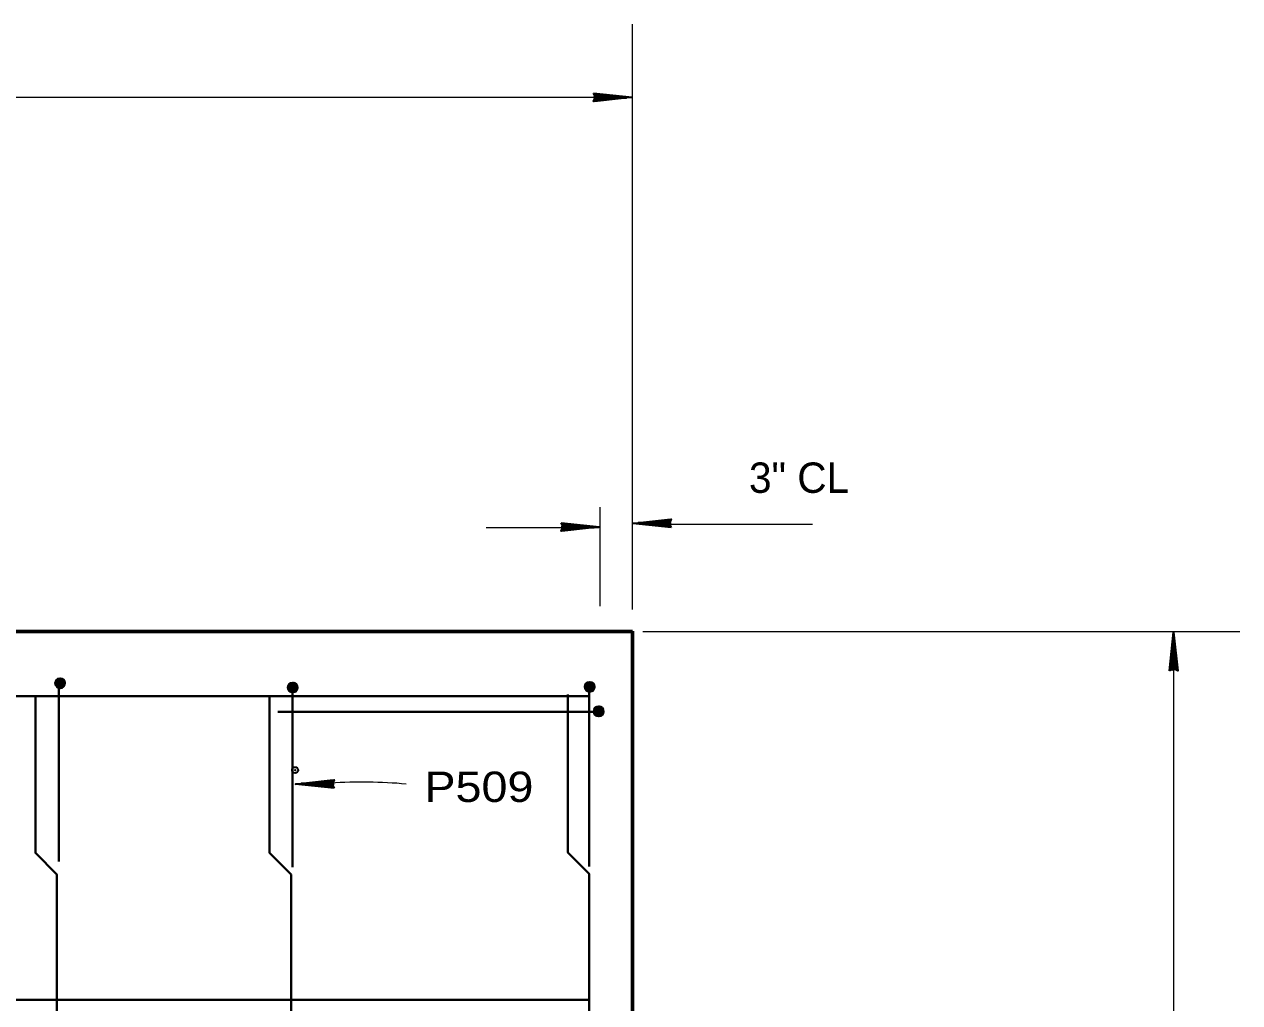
# Model space of a CAD drawing. Extents: x 4.49 to 7.69, y 0.28 to 2.27.
# Drawn here: x 5.2955 to 5.6291, y 0.9139 to 1.1824 of the extents above; entities that cross this region are included whole.
import ezdxf

# ---------------------------------------------------------------- set-up
doc = ezdxf.new("R2010")
doc.units = 0
doc.header["$LTSCALE"] = 0.0033
doc.header["$PDMODE"] = 32
doc.header["$PDSIZE"] = 0.00165
doc.layers.add('1', color=7, linetype='Continuous', lineweight=35)

msp = doc.modelspace()

# ---------------------------------------------------------------- linework, layer by layer
at = {"layer": '1', "lineweight": 13}
for p, q in [((5.462417, 1.021833), (5.462417, 1.182417)), ((5.453583, 1.02275), (5.453583, 1.049917)), ((5.462417, 1.049083), (5.462417, 1.049417)), ((5.462417, 1.049083), (5.4625, 1.049083)), ((5.42225, 1.044333), (5.453167, 1.044333)), ((5.473083, 1.04525), (5.511833, 1.04525)), ((5.46525, 1.01575), (5.629083, 1.01575)), ((5.610917, 1.013917), (5.610917, 0.599083))]:
    msp.add_line(p, q, dxfattribs=at)
at = {"layer": '1'}
for p, q in [((5.45175, 1.162417), (5.462333, 1.162417)), ((5.451917, 1.16175), (5.45925, 1.1625)), ((5.452, 1.163417), (5.459833, 1.1625)), ((5.452, 1.163417), (5.459833, 1.1625)), ((5.452, 1.163333), (5.459833, 1.1625)), ((5.452, 1.16325), (5.459833, 1.162417)), ((5.452, 1.16325), (5.459833, 1.16225)), ((5.452, 1.161583), (5.459333, 1.162417)), ((5.452, 1.1615), (5.459333, 1.16225)), ((5.452, 1.161333), (5.459333, 1.162167)), ((5.442833, 1.0445), (5.453417, 1.0445)), ((5.443, 1.043833), (5.450333, 1.044583)), ((5.443083, 1.0455), (5.450917, 1.044583)), ((5.443083, 1.0455), (5.450917, 1.044583)), ((5.443083, 1.045417), (5.450917, 1.044583)), ((5.443083, 1.045333), (5.450917, 1.0445)), ((5.443083, 1.045333), (5.450917, 1.044333)), ((5.443083, 1.043667), (5.450417, 1.0445)), ((5.443083, 1.043583), (5.450417, 1.044333)), ((5.443083, 1.043417), (5.450417, 1.04425)), ((5.473083, 1.045417), (5.4625, 1.045417)), ((5.472833, 1.044583), (5.465, 1.045583)), ((5.472833, 1.044583), (5.465, 1.045417)), ((5.472833, 1.044417), (5.465, 1.045333)), ((5.472833, 1.044417), (5.465, 1.045333)), ((5.472833, 1.0445), (5.465, 1.045333)), ((5.472833, 1.0465), (5.4655, 1.045667)), ((5.472833, 1.046333), (5.4655, 1.045583)), ((5.472833, 1.04625), (5.4655, 1.045417)), ((5.472917, 1.046083), (5.465583, 1.045333)), ((5.610917, 1.005), (5.610917, 1.015583)), ((5.609917, 1.00525), (5.610833, 1.013083)), ((5.609917, 1.00525), (5.610833, 1.013083)), ((5.61, 1.00525), (5.610833, 1.013083)), ((5.610083, 1.00525), (5.610917, 1.013083)), ((5.610083, 1.00525), (5.611083, 1.013083)), ((5.611583, 1.005167), (5.610833, 1.0125)), ((5.61175, 1.00525), (5.610917, 1.012583)), ((5.611833, 1.00525), (5.611083, 1.012583)), ((5.612, 1.00525), (5.611167, 1.012583)), ((5.380333, 0.973083), (5.3725, 0.974083)), ((5.380333, 0.975), (5.373, 0.974167)), ((5.380333, 0.974833), (5.373, 0.974083)), ((5.380333, 0.97475), (5.373, 0.973917)), ((5.380417, 0.974583), (5.373083, 0.973833)), ((5.380583, 0.973917), (5.37, 0.973917)), ((5.380333, 0.973083), (5.3725, 0.973917)), ((5.380333, 0.972917), (5.3725, 0.973833)), ((5.380333, 0.972917), (5.3725, 0.973833)), ((5.380333, 0.973), (5.3725, 0.973833))]:
    msp.add_line(p, q, dxfattribs=at)
at = {"layer": '1', "lineweight": 60}
for p, q in [((5.122333, 1.01575), (5.462417, 1.01575)), ((5.462417, 1.01575), (5.462417, 1.015917))]:
    msp.add_line(p, q, dxfattribs=at)
at = {"layer": '1', "lineweight": 40}
for p, q in [((5.304417, 1.00075), (5.30475, 1.002667)), ((5.304583, 1.000667), (5.304917, 1.002667)), ((5.304583, 1.001667), (5.306083, 1.001583)), ((5.304583, 1.001583), (5.306083, 1.0015)), ((5.304583, 1.0015), (5.306083, 1.001417)), ((5.304583, 1.001417), (5.306083, 1.001333)), ((5.304583, 1.001333), (5.306083, 1.00125)), ((5.304583, 1.00125), (5.306083, 1.001167)), ((5.304583, 1.001167), (5.306083, 1.001083)), ((5.304583, 1.001), (5.306083, 1.000917)), ((5.304583, 1.000917), (5.306083, 1.000833)), ((5.304583, 1.000833), (5.306083, 1.00075)), ((5.304583, 1.00075), (5.306083, 1.000667)), ((5.304583, 1.000667), (5.306083, 1.000583)), ((5.304667, 1.00275), (5.306167, 1.002667)), ((5.304667, 1.000667), (5.305, 1.002667)), ((5.304667, 1.002583), (5.306167, 1.0025)), ((5.304667, 1.0025), (5.306167, 1.002417)), ((5.304667, 1.002417), (5.306167, 1.002333)), ((5.304667, 1.002333), (5.306167, 1.00225)), ((5.304667, 1.00225), (5.306167, 1.002167)), ((5.304667, 1.002167), (5.306167, 1.002083)), ((5.304667, 1.002083), (5.306167, 1.002)), ((5.304667, 1.002083), (5.306167, 1.002)), ((5.304667, 1.002), (5.306167, 1.001833)), ((5.304667, 1.001833), (5.306167, 1.001667)), ((5.30475, 1.000667), (5.305167, 1.002667)), ((5.304833, 1.000667), (5.30525, 1.002667)), ((5.305, 1.000667), (5.305333, 1.002583)), ((5.305, 1.002), (5.305, 0.952667)), ((5.305083, 1.000583), (5.305417, 1.002583)), ((5.305167, 1.000583), (5.305583, 1.002583)), ((5.30525, 1.000583), (5.305667, 1.0025)), ((5.305333, 1.000583), (5.30575, 1.0025)), ((5.3055, 1.0005), (5.305917, 1.0025)), ((5.30575, 1.0005), (5.306083, 1.0025)), ((5.305833, 1.0005), (5.306167, 1.002417)), ((5.305917, 1.0005), (5.30625, 1.002417)), ((5.306, 1.000417), (5.306333, 1.002417)), ((5.36825, 0.999583), (5.368583, 1.0015)), ((5.368417, 0.9995), (5.36875, 1.0015)), ((5.3685, 1.001583), (5.37, 1.0015)), ((5.3685, 0.9995), (5.368833, 1.0015)), ((5.3685, 1.001417), (5.37, 1.001333)), ((5.3685, 1.001333), (5.37, 1.00125)), ((5.3685, 1.00125), (5.37, 1.001167)), ((5.3685, 1.001167), (5.37, 1.001083)), ((5.3685, 1.001083), (5.37, 1.001)), ((5.3685, 1.001), (5.37, 1.000917)), ((5.3685, 1.000917), (5.37, 1.000833)), ((5.3685, 1.000917), (5.37, 1.000833)), ((5.3685, 1.000833), (5.37, 1.000667)), ((5.3685, 1.000667), (5.37, 1.0005)), ((5.368583, 0.9995), (5.369, 1.0015)), ((5.368667, 0.9995), (5.369083, 1.0015)), ((5.368833, 0.9995), (5.369167, 1.001417)), ((5.368917, 0.999417), (5.36925, 1.001417)), ((5.369, 0.999417), (5.369417, 1.001417)), ((5.369083, 0.999417), (5.3695, 1.001333)), ((5.369167, 0.999417), (5.369583, 1.001333)), ((5.369333, 0.999333), (5.36975, 1.001333)), ((5.369583, 0.999333), (5.369917, 1.001333)), ((5.369667, 0.999333), (5.37, 1.00125)), ((5.36975, 0.999333), (5.370083, 1.00125)), ((5.369833, 0.99925), (5.370167, 1.00125)), ((5.44975, 0.99975), (5.450083, 1.001667)), ((5.449917, 0.999667), (5.45025, 1.001667)), ((5.449917, 1.000667), (5.451417, 1.000583)), ((5.45, 1.00175), (5.4515, 1.001667)), ((5.45, 0.999667), (5.450333, 1.001667)), ((5.45, 1.001583), (5.4515, 1.0015)), ((5.45, 1.0015), (5.4515, 1.001417)), ((5.45, 1.001417), (5.4515, 1.001333)), ((5.45, 1.001333), (5.4515, 1.00125)), ((5.45, 1.00125), (5.4515, 1.001167)), ((5.45, 1.001167), (5.4515, 1.001083)), ((5.45, 1.001083), (5.4515, 1.001)), ((5.45, 1.001083), (5.4515, 1.001)), ((5.45, 1.001), (5.4515, 1.000833)), ((5.45, 1.000833), (5.4515, 1.000667)), ((5.450083, 0.999667), (5.4505, 1.001667)), ((5.450167, 0.999667), (5.450583, 1.001667)), ((5.450333, 0.999667), (5.450667, 1.001583)), ((5.450417, 0.999583), (5.45075, 1.001583)), ((5.4505, 0.999583), (5.450917, 1.001583)), ((5.450583, 0.999583), (5.451, 1.0015)), ((5.450667, 0.999583), (5.451083, 1.0015)), ((5.450833, 0.9995), (5.45125, 1.0015)), ((5.451083, 0.9995), (5.451417, 1.0015)), ((5.451167, 0.9995), (5.4515, 1.001417)), ((5.45125, 0.9995), (5.451583, 1.001417)), ((5.451333, 0.999417), (5.451667, 1.001417)), ((5.368417, 1.0005), (5.369917, 1.000417)), ((5.368417, 1.000417), (5.369917, 1.000333)), ((5.368417, 1.000333), (5.369917, 1.00025)), ((5.368417, 1.00025), (5.369917, 1.000167)), ((5.368417, 1.000167), (5.369917, 1.000083)), ((5.368417, 1.000083), (5.369917, 1)), ((5.368417, 1), (5.369917, 0.999917)), ((5.368417, 0.999833), (5.369917, 0.99975)), ((5.368417, 0.99975), (5.369917, 0.999667)), ((5.368417, 0.999667), (5.369917, 0.999583)), ((5.368417, 0.999583), (5.369917, 0.9995)), ((5.368417, 0.9995), (5.369917, 0.999417)), ((5.369167, 1.000417), (5.369167, 0.951083)), ((5.449917, 1.000583), (5.451417, 1.0005)), ((5.449917, 1.0005), (5.451417, 1.000417)), ((5.449917, 1.000417), (5.451417, 1.000333)), ((5.449917, 1.000333), (5.451417, 1.00025)), ((5.449917, 1.00025), (5.451417, 1.000167)), ((5.449917, 1.000167), (5.451417, 1.000083)), ((5.449917, 1), (5.451417, 0.999917)), ((5.449917, 0.999917), (5.451417, 0.999833)), ((5.449917, 0.999833), (5.451417, 0.99975)), ((5.449917, 0.99975), (5.451417, 0.999667)), ((5.449917, 0.999667), (5.451417, 0.999583)), ((5.450583, 1.000583), (5.450583, 0.95125)), ((5.452, 0.993167), (5.452083, 0.994667)), ((5.452167, 0.993167), (5.45225, 0.994667)), ((5.454167, 0.993667), (5.452167, 0.994083)), ((5.45225, 0.993167), (5.452333, 0.994667)), ((5.45425, 0.99425), (5.45225, 0.994583)), ((5.45425, 0.994), (5.45225, 0.994417)), ((5.454167, 0.993833), (5.45225, 0.99425)), ((5.454167, 0.99375), (5.45225, 0.994167)), ((5.454333, 0.9945), (5.452333, 0.994833)), ((5.45425, 0.994417), (5.452333, 0.99475)), ((5.452333, 0.993167), (5.452417, 0.994667)), ((5.45425, 0.994333), (5.452333, 0.994667)), ((5.452417, 0.993167), (5.4525, 0.994667)), ((5.4525, 0.993167), (5.452583, 0.994667)), ((5.452583, 0.993167), (5.452667, 0.994667)), ((5.452667, 0.993167), (5.45275, 0.994667)), ((5.452667, 0.993167), (5.45275, 0.994667)), ((5.45275, 0.993167), (5.452917, 0.994667)), ((5.452917, 0.993167), (5.453083, 0.994667)), ((5.453083, 0.993083), (5.453167, 0.994583)), ((5.453167, 0.993083), (5.45325, 0.994583)), ((5.45325, 0.993083), (5.453333, 0.994583)), ((5.453333, 0.993083), (5.453417, 0.994583)), ((5.453417, 0.993083), (5.4535, 0.994583)), ((5.4535, 0.993083), (5.453583, 0.994583)), ((5.453583, 0.993083), (5.453667, 0.994583)), ((5.45375, 0.993083), (5.453833, 0.994583)), ((5.453833, 0.993083), (5.453917, 0.994583)), ((5.453917, 0.993083), (5.454, 0.994583)), ((5.454, 0.993083), (5.454083, 0.994583)), ((5.454083, 0.993083), (5.454167, 0.994583)), ((5.365083, 0.99375), (5.453167, 0.99375)), ((5.3675, 0.99375), (5.453167, 0.99375)), ((5.454083, 0.993333), (5.452083, 0.99375)), ((5.454083, 0.99325), (5.452083, 0.993667)), ((5.454083, 0.993167), (5.452083, 0.9935)), ((5.454083, 0.993083), (5.452083, 0.993417)), ((5.454, 0.992917), (5.452083, 0.99325)), ((5.454167, 0.993583), (5.452167, 0.993917)), ((5.454083, 0.9935), (5.452167, 0.993833)), ((5.122167, 0.914667), (5.450417, 0.914667))]:
    msp.add_line(p, q, dxfattribs=at)
at = {"layer": '1', "lineweight": 13}
msp.add_lwpolyline([(4.878417, 1.162417), (5.18125, 1.162417), (5.46175, 1.162417)], dxfattribs=at)
at = {"layer": '1'}
for points in [[(5.45175, 1.1635), (5.462333, 1.162417), (5.45175, 1.16125), (5.452333, 1.162417)], [(5.4525, 1.1625), (5.457167, 1.162583), (5.457167, 1.1625), (5.45625, 1.1625), (5.4525, 1.162583), (5.4555, 1.162667), (5.452333, 1.16275), (5.454583, 1.162833), (5.452333, 1.162917), (5.455833, 1.162667), (5.4605, 1.1625), (5.459583, 1.16225), (5.460833, 1.16225), (5.4525, 1.16225), (5.454917, 1.162083), (5.452333, 1.162083), (5.457667, 1.1625), (5.452333, 1.161833)], [(5.442833, 1.045583), (5.453417, 1.0445), (5.442833, 1.043333), (5.443417, 1.0445)], [(5.443583, 1.044583), (5.44825, 1.044667), (5.44825, 1.044583), (5.447333, 1.044583), (5.443583, 1.044667), (5.446583, 1.04475), (5.443417, 1.044833), (5.445667, 1.044917), (5.443417, 1.045), (5.446917, 1.04475), (5.451583, 1.044583), (5.450667, 1.044333), (5.451917, 1.044333), (5.443583, 1.044333), (5.446, 1.044167), (5.443417, 1.044167), (5.44875, 1.044583), (5.443417, 1.043917)], [(5.473083, 1.044333), (5.4625, 1.045417), (5.473083, 1.046583), (5.4725, 1.045417)], [(5.472333, 1.045333), (5.467667, 1.04525), (5.467667, 1.045333), (5.468583, 1.045333), (5.472333, 1.04525), (5.469333, 1.045167), (5.4725, 1.045083), (5.47025, 1.045), (5.4725, 1.044917), (5.469, 1.045167), (5.464333, 1.045333), (5.46525, 1.045583), (5.464, 1.045583), (5.472333, 1.045583), (5.469917, 1.04575), (5.4725, 1.04575), (5.467167, 1.045333), (5.4725, 1.046)], [(5.609833, 1.005), (5.610917, 1.015583), (5.612083, 1.005), (5.610917, 1.005583)], [(5.610833, 1.00575), (5.61075, 1.010417), (5.610833, 1.010417), (5.610833, 1.0095), (5.61075, 1.00575), (5.610667, 1.00875), (5.610583, 1.005583), (5.6105, 1.007833), (5.610417, 1.005583), (5.610667, 1.009083), (5.610833, 1.01375), (5.611083, 1.012833), (5.611083, 1.014083), (5.611083, 1.00575), (5.61125, 1.008167), (5.61125, 1.005583), (5.610833, 1.010917), (5.6115, 1.005583)], [(5.380583, 0.972833), (5.37, 0.973917), (5.380583, 0.975083), (5.38, 0.973917)], [(5.379833, 0.973833), (5.375167, 0.97375), (5.375167, 0.973833), (5.376083, 0.973833), (5.379833, 0.97375), (5.376833, 0.973667), (5.38, 0.973583), (5.37775, 0.9735), (5.38, 0.973417), (5.3765, 0.973667), (5.371833, 0.973833), (5.37275, 0.974083), (5.3715, 0.974083), (5.379833, 0.974083), (5.377417, 0.97425), (5.38, 0.97425), (5.374667, 0.973833), (5.38, 0.9745)]]:
    msp.add_lwpolyline(points, close=True, dxfattribs=at)
for points in [[(5.4525, 1.1625), (5.452083, 1.16325), (5.452333, 1.163), (5.4525, 1.162667), (5.45275, 1.16275), (5.452583, 1.163083), (5.452417, 1.162333), (5.45225, 1.161833), (5.452, 1.161417)], [(5.443583, 1.044583), (5.443167, 1.045333), (5.443417, 1.045083), (5.443583, 1.04475), (5.443833, 1.044833), (5.443667, 1.045167), (5.4435, 1.044417), (5.443333, 1.043917), (5.443083, 1.0435)], [(5.472333, 1.045333), (5.47275, 1.044583), (5.4725, 1.044833), (5.472333, 1.045167), (5.472083, 1.045083), (5.47225, 1.04475), (5.472417, 1.0455), (5.472583, 1.046), (5.472833, 1.046417)], [(5.610833, 1.00575), (5.610083, 1.005333), (5.610333, 1.005583), (5.610667, 1.00575), (5.610583, 1.006), (5.61025, 1.005833), (5.611, 1.005667), (5.6115, 1.0055), (5.611917, 1.00525)], [(5.379833, 0.973833), (5.38025, 0.973083), (5.38, 0.973333), (5.379833, 0.973667), (5.379583, 0.973583), (5.37975, 0.97325), (5.379917, 0.974), (5.380083, 0.9745), (5.380333, 0.974917)]]:
    msp.add_lwpolyline(points, dxfattribs=at)
at = {"layer": '1', "lineweight": 60}
msp.add_lwpolyline([(5.462417, 1.01575), (5.462417, 0.682417), (5.54575, 0.682417), (5.54575, 0.599083)], dxfattribs=at)
at = {"layer": '1', "lineweight": 40}
for points in [[(5.305417, 1.00025), (5.305083, 1.002833), (5.304583, 1.0005), (5.305667, 1.002833), (5.306083, 1.000417), (5.306417, 1.002417), (5.304333, 1.002417), (5.306667, 1.0015), (5.304083, 1.00175), (5.306417, 1.00075), (5.304083, 1.001083), (5.306667, 1.001917), (5.304917, 1.000333), (5.30475, 1.00275), (5.306583, 1.001083), (5.304167, 1.002167), (5.304583, 1.0005), (5.306083, 1.000417), (5.306667, 1.0015), (5.306417, 1.002417), (5.305667, 1.002833), (5.30475, 1.00275), (5.304167, 1.002167), (5.30525, 1.0015), (5.306167, 1.002667), (5.306417, 1.00075), (5.30525, 1.0015), (5.30475, 1.000417), (5.304083, 1.001417), (5.305167, 1.0015), (5.306417, 1.002333), (5.305167, 1.000333), (5.304833, 1.001667), (5.304333, 1.002417)], [(5.36925, 0.999083), (5.368917, 1.001667), (5.368417, 0.999333), (5.3695, 1.001667), (5.369917, 0.99925), (5.37025, 1.00125), (5.368167, 1.00125), (5.3705, 1.000333), (5.367917, 1.000583), (5.37025, 0.999583), (5.367917, 0.999917), (5.3705, 1.00075), (5.36875, 0.999167), (5.368583, 1.001583), (5.370417, 0.999917), (5.368, 1.001), (5.368417, 0.999333), (5.369917, 0.99925), (5.3705, 1.000333), (5.37025, 1.00125), (5.3695, 1.001667), (5.368583, 1.001583), (5.368, 1.001), (5.369083, 1.000333), (5.37, 1.0015), (5.37025, 0.999583), (5.369083, 1.000333), (5.368583, 0.99925), (5.367917, 1.00025), (5.369, 1.000333), (5.37025, 1.001167), (5.369, 0.999167), (5.368667, 1.0005), (5.368167, 1.00125)], [(5.45075, 0.99925), (5.450417, 1.001833), (5.449917, 0.9995), (5.451, 1.001833), (5.451417, 0.999417), (5.45175, 1.001417), (5.449667, 1.001417), (5.452, 1.0005), (5.449417, 1.00075), (5.45175, 0.99975), (5.449417, 1.000083), (5.452, 1.000917), (5.45025, 0.999333), (5.450083, 1.00175), (5.451917, 1.000083), (5.4495, 1.001167), (5.449917, 0.9995), (5.451417, 0.999417), (5.452, 1.0005), (5.45175, 1.001417), (5.451, 1.001833), (5.450083, 1.00175), (5.4495, 1.001167), (5.450583, 1.0005), (5.4515, 1.001667), (5.45175, 0.99975), (5.450583, 1.0005), (5.450083, 0.999417), (5.449417, 1.000417), (5.4505, 1.0005), (5.45175, 1.001333), (5.4505, 0.999333), (5.450167, 1.000667), (5.449667, 1.001417)], [(4.896833, 0.998), (5.122333, 0.998), (5.4505, 0.998)], [(5.298583, 0.998333), (5.298583, 0.955), (5.3045, 0.949083), (5.3045, 0.74075), (5.298583, 0.734833), (5.298583, 0.688583)], [(5.362833, 0.998333), (5.362833, 0.955), (5.36875, 0.949083), (5.36875, 0.74075), (5.362833, 0.734833), (5.362833, 0.688583)], [(5.444667, 0.9985), (5.444667, 0.955167), (5.450583, 0.94925), (5.450583, 0.740917), (5.444667, 0.735), (5.444667, 0.68875)], [(5.4545, 0.993917), (5.451917, 0.993583), (5.45425, 0.993083), (5.451917, 0.994167), (5.454333, 0.994583), (5.452333, 0.994917), (5.452333, 0.992833), (5.45325, 0.995167), (5.453, 0.992583), (5.454, 0.994917), (5.453667, 0.992583), (5.452833, 0.995167), (5.454417, 0.993417), (5.452, 0.99325), (5.453667, 0.995083), (5.452583, 0.992667), (5.45425, 0.993083), (5.454333, 0.994583), (5.45325, 0.995167), (5.452333, 0.994917), (5.451917, 0.994167), (5.452, 0.99325), (5.452583, 0.992667), (5.45325, 0.99375), (5.452083, 0.994667), (5.454, 0.994917), (5.45325, 0.99375), (5.454333, 0.99325), (5.453333, 0.992583), (5.45325, 0.993667), (5.452417, 0.994917), (5.454417, 0.993667), (5.453083, 0.993333), (5.452333, 0.992833)]]:
    msp.add_lwpolyline(points, dxfattribs=at)
for centre in [(5.305367, 1.001583), (5.3692, 1.000417), (5.4507, 1.000583), (5.453167, 0.993867)]:
    msp.add_circle(centre, 0.00132, dxfattribs=at)
at = {"layer": '1', "lineweight": 13}
msp.add_arc((5.388323, 0.835412), 0.139025, 85.04405, 93.56983, dxfattribs=at)
at = {"layer": '1'}
msp.add_point((5.369833, 0.97775), dxfattribs=at)

# ---------------------------------------------------------------- texts
msp.add_text('3" CL', height=0.008334, dxfattribs=at).set_placement((5.494417, 1.053833))
at = {"layer": '1', "width": 1.15}
msp.add_text('P509', height=0.008334, dxfattribs=at).set_placement((5.405333, 0.969))

doc.saveas('drawing.dxf')
